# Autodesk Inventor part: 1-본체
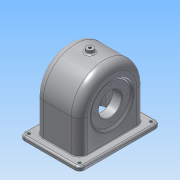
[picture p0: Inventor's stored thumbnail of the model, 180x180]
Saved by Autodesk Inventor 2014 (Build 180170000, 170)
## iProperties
Created: 2016-01
Part Number: 1-본체
Material: 알루미늄 6061
Document SubType Name: Modeling
Designer: Administrator
Density: 2.71 g/cm^3
Appearance: 알루미늄 - 평지
Mass: 809.681 g
Surface Area: 999.193 cm^2
Volume: 298.775 cm^3
Author: Administrator
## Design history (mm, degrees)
sketch "스케치1"
  geometry: L1 (-44, -70)-(44, -70); L2 (52, -62)-(52, 62); L3 (44, 70)-(-44, 70); L4 (-52, 62)-(-52, -62); L5 (-52, -70)-(52, 70); L6 (52, -70)-(-52, 70); A1 r 8 centre (-44, 62) between (-44, 70) and (-52, 62); A2 r 8 centre (44, 62) between (52, 62) and (44, 70); A3 r 8 centre (-44, -62) between (-52, -62) and (-44, -70); A4 r 8 centre (44, -62) between (44, -70) and (52, -62); 1 further point
  constraints: 12 end point, 8 point on circle, 8 point on line, 8 tangent, 4 centre point, 3 equal radius, 2 midpoint, 2 parallel, 1 horizontal, 1 perpendicular
  dimensions: "d0" = 104 distance of L5.end L6.end; "d1" = 140 distance of L6.start L5.end; "d2" = 8 radius of A1
extrude "돌출1" new body sketch "스케치1" distance "d3" = 7; taper "d4" = 0 deg
node "작업 평면1"
sketch "스케치3"
  geometry: L1 (-7, 124)-(-7, 0) reference; L2 (-64, 11)-(-7, 11); L3 (-64, 113)-(-7, 113); L4 (-64, 5)-(-7, 5); L5 (-64, 119)-(-7, 119); L6 (-7, 5)-(-7, 119); A1 r 57 centre (-64, 62) between (-64, 119) and (-64, 5); A2 r 51 centre (-64, 62) between (-64, 113) and (-64, 11); 1 further point
  constraints: 10 end point, 4 perpendicular, 4 point on circle, 4 point on line, 4 tangent, 2 centre point, 1 coincident, 1 collinear
  dimensions: "d6" = 57 radius of A1; "d7" = 64 distance of point (0, 62) A1.centre; "d8" = 0 vertical distance of A1.centre point (0, 62); "d12" = 102 diameter of A2
extrude "돌출3" join sketch "스케치3" stored distance "d15" = 77; taper "d16" = 0 deg
extrude "돌출4" cut sketch "스케치3" stored distance "d17" = 67; taper "d18" = 0 deg
node "작업 평면3"
sketch "스케치5"
  geometry: L1 (-38.5, 57)-(-38.5, -57) reference; L2 (38.5, -57)-(38.5, 57) reference; L3 (0, 0)-(67.019, 0); L4 (48.5, 0)-(48.5, 31); L5 (48.5, 31)-(38.5, 31); L6 (38.5, 31)-(38.5, 0)
  constraints: 8 end point, 3 perpendicular, 3 point on line, 1 midpoint
  dimensions: "d20" = 62 diameter of L5 L3; "d21" = 10 distance between parallel lines of L4 L2
revolve "회전1" sketch "스케치5" stored, may be unused: angle "d22" = 90 deg
sketch "스케치6"
  geometry: L1 (48.5, -31)-(48.5, 31) reference; L2 (-33.5, 51)-(-33.5, -51) reference; L3 (38.5, 57)-(-38.5, 57) reference; L4 (0, 0)-(-44.74, 0); L5 (-33.5, 39.747)-(-19.5, 28); L6 (-19.5, 28)-(-19.5, 0); L7 (-33.5, 39.747)-(-33.5, 0); L8 (-38.5, 57)-(-38.5, -57) reference; 1 further point
  constraints: 8 end point, 3 point on line, 1 coincident, 1 midpoint, 1 parallel, 1 perpendicular
  dimensions: "d26" = 33.5 distance from line of point (0, 0) L2 (derived); "d27" = 56 diameter of L5.end L4; "d28" = 50 deg angle of L6 L5; "d30" = 19 distance between parallel lines of L8 L6
revolve "회전2" sketch "스케치6" stored, may be unused: angle "d31" = 90 deg
sketch "스케치7"
  geometry: L1 (0, 0)-(57.526, 0); L2 (33.5, -51)-(33.5, 51) reference; L3 (33.5, 20)-(43.5, 20); L4 (33.5, 20)-(33.5, 0); L5 (-33.5, 39.747)-(-19.5, 28) reference; L6 (-19.5, -28)-(-19.5, 28) reference; L7 (0, 0)-(-45.884, 0); L8 (-19.5, 20)-(-35.5, 20); L9 (-35.5, 20)-(-35.5, 34.899); L10 (-38.5, 57)-(-38.5, -57) reference; L11 (-35.5, 34.899)-(-38.5, 37.416); L12 (-38.5, 37.416)-(-38.5, 0); L13 (-19.5, 20)-(-19.5, 0); L14 (-19.5, 0)-(-38.5, 0); L15 (33.5, 0)-(43.5, 0); L16 (48.5, -31)-(48.5, 31) reference; L17 (43.5, 20)-(48.5, 20); L18 (48.5, 20)-(48.5, 0); L19 (48.5, 0)-(43.5, 0)
  constraints: 28 end point, 6 point on line, 4 midpoint, 4 perpendicular, 3 collinear, 2 parallel, 1 horizontal
  dimensions: "d32" = 40 diameter of L3 L1; "d34" = 5 distance between parallel lines of L11 L5; "d35" = 40 diameter of L8 L7; "d36" = 3 distance between parallel lines of L9 L10
revolve "회전3" sketch "스케치7" stored, may be unused: angle "d37" = 90 deg
node "작업 평면4"
sketch "스케치8"
  geometry: C1 r 6 at (0, 0); 1 further point
  constraints: 1 centre point, 1 coincident
  dimensions: "d39" = 12 diameter of C1
extrude "돌출5" join sketch "스케치8" stored distance "d40" = 67; taper "d41" = 0 deg
hole "구멍1" diameter "d44" = 4.459; stored, may be unused: countersink angle "d48" = 90 deg, drill point angle "d50" = 118 deg; dims "d42" = 10, "d43" = 10, "d45" = 6, "d46" = 4, "d47" = 2, "d49" = 8
sketch "스케치9"
  geometry: C1 r 20 at (0, 0) reference; C2 r 31 at (0, 0) reference; A1 r 24 centre (0, 0) between (0, 24) and (-24, 0); 3 further points
  constraints: 4 point on circle, 2 horizontal alignment, 2 vertical alignment, 1 centre point, 1 coincident
  dimensions: "d51" = 48 diameter of A1
hole "구멍2" sketch "스케치9" at (0, 24), (-24, 0), (0, -24), (24, 0) diameter "d52" = 2.459; stored, may be unused: countersink angle "d56" = 90 deg, drill point angle "d58" = 118 deg; dims "d53" = 6, "d54" = 4, "d55" = 2, "d57" = 8
fillet "모깎기1" dims "d59" = 3
chamfer "모따기1" distance "d60" = 1; stored, may be unused: second distance "d61" = 2, angle "d62" = 45 deg
fillet "모깎기2" dims "d63" = 3
sketch "스케치10"
  geometry: C1 r 21 at (0, 0) reference; C2 r 33.5 at (0, 0) reference; A1 r 28 centre (0, 0) between (-28, 0) and (0, -28); 3 further points
  constraints: 4 point on circle, 2 horizontal alignment, 2 vertical alignment, 1 centre point, 1 coincident
  dimensions: "d64" = 56 diameter of A1
hole "구멍3" sketch "스케치10" at (-28, 0), (0, -28), (28, 0), (0, 28) diameter "d65" = 2.459; stored, may be unused: countersink angle "d69" = 90 deg, drill point angle "d71" = 118 deg; dims "d66" = 7, "d67" = 4, "d68" = 2, "d70" = 9
fillet "모깎기3" dims "d72" = 3, "d73" = 14
sketch "스케치12"
  geometry: L1 (-33.5, -51)-(33.5, -51); L2 (33.5, -51)-(33.5, 51); L3 (33.5, 51)-(-33.5, 51); L4 (-33.5, 51)-(-33.5, -51); L5 (-33.5, -51)-(33.5, 51); L6 (33.5, -51)-(-33.5, 51); 1 further point
  constraints: 12 end point, 2 midpoint, 2 parallel, 1 horizontal, 1 perpendicular
  dimensions: "d79" = 67 distance of L2.end L3.end; "d80" = 102 distance of L1.end L2.end
extrude "돌출7" cut sketch "스케치12" stored distance "d81" = 67; taper "d82" = 0 deg
sketch "스케치13"
  geometry: L1 (-19.5, 64)-(68.5, 64) reference; L2 (63, 0)-(63, 57) reference; 3 further points
  constraints: 1 coincident, 1 other
  dimensions: "d83" = 30 distance from line of L1 point (24.5, 34); "d84" = 38.5 distance from line of point (24.5, 34) L2
feature "엠보싱1" sketch "스케치13" dims "d0" = 104, "d1" = 140, "d2" = 8, "d6" = 57, "d7" = 64, "d8" = 0, "d12" = 102, "d85" = 0.5, "d86" = 0
hole "구멍4" diameter "d89" = 5; stored, may be unused: countersink angle "d93" = 90 deg, drill point angle "d95" = 118 deg; dims "d87" = 10, "d88" = 10, "d90" = 7, "d91" = 4, "d92" = 2, "d94" = 9
fillet "모깎기4" dims "d102" = 9, "d103" = 3
fillet "모깎기5" dims "d104" = 1
node "솔리드1"
pattern_linear "직사각형 패턴1" dims "d98" = 88, "d101" = 124
other parameters: "d38" = -127
